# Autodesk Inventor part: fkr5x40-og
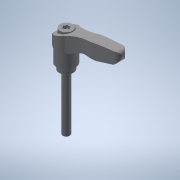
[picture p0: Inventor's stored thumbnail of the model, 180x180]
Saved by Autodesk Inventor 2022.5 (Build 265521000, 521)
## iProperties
Created: 2016-12
Part Number: fkr5x40-og
Material: 一般
Document SubType Name: Modeling
Designer: imaocorp
Density: 1 g/cm^3
Appearance: 既定
Author: imaocorp
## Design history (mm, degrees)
node "fkr5x40-og.x_t1"
node "K1000_105040_012"
node "Base1"
